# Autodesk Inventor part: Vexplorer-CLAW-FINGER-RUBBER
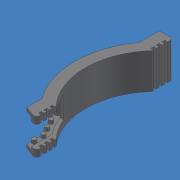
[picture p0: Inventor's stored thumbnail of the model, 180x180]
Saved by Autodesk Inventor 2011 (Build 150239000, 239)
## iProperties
Created: 2007-10
Part Number: Vexplorer-CLAW-FINGER-RUBBER
Document SubType Name: Modeling
Material: Rubber
Density: 0.93 g/cm^3
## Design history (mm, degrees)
feature "Base1"
body "Solid1"
